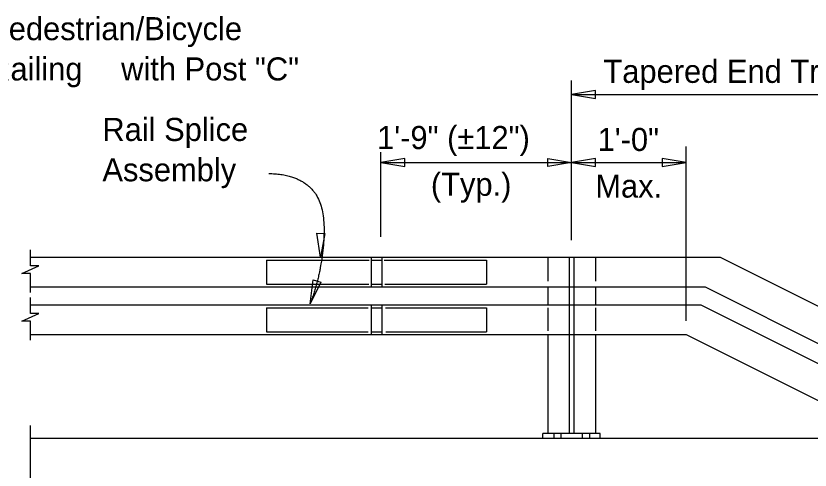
# Model space of a CAD drawing. Extents: x 120680.2 to 120752.3, y 120667.6 to 120707.3.
# Drawn here: x 120705.13 to 120712.07, y 120699.52 to 120703.49 of the extents above; entities that cross this region are included whole.
import ezdxf

# ---------------------------------------------------------------- set-up
doc = ezdxf.new("R2010")
doc.units = 0
for name, color, linetype in [('Default', 7, 'Continuous'), ('Dimension', 7, 'Continuous'), ('ParapetConc', 7, 'Continuous'), ('PedRail', 7, 'Continuous'), ('TextStructures', 7, 'Continuous')]:
    doc.layers.add(name, color=color, linetype=linetype)

msp = doc.modelspace()

# ---------------------------------------------------------------- linework, layer by layer
at = {"layer": 'Default'}
msp.add_lwpolyline([(120709.7737, 120702.2391), (120709.982, 120702.2038), (120709.7737, 120702.1686)], close=True, dxfattribs=at)
at = {"layer": 'Dimension'}
for p, q in [((120709.982, 120701.5249), (120709.982, 120702.92)), ((120710.982, 120700.8207), (120710.982, 120702.3438)), ((120708.3152, 120701.556), (120708.3152, 120702.2949))]:
    msp.add_line(p, q, dxfattribs=at)
for points in [[(120709.982, 120702.7991), (120710.1902, 120702.7638), (120710.1902, 120702.8344)], [(120708.3152, 120702.2038), (120708.5235, 120702.1686), (120708.5235, 120702.2391)], [(120709.982, 120702.2038), (120710.1902, 120702.1686), (120710.1902, 120702.2391)], [(120710.982, 120702.2038), (120710.7737, 120702.2391), (120710.7737, 120702.1686)], [(120707.8252, 120701.5859), (120707.7884, 120701.3779), (120707.7547, 120701.5864)], [(120707.7918, 120701.1593), (120707.6976, 120700.9703), (120707.7243, 120701.1798)]]:
    msp.add_lwpolyline(points, close=True, dxfattribs=at)
for points in [[(120708.3152, 120702.2038), (120709.982, 120702.2038)], [(120705.2543, 120701.069), (120705.2543, 120701.2356), (120705.1768, 120701.2356), (120705.3268, 120701.3018), (120705.2543, 120701.3018), (120705.2543, 120701.4427)], [(120705.2543, 120700.6523), (120705.2543, 120700.8189), (120705.1768, 120700.8189), (120705.3268, 120700.8852), (120705.2543, 120700.8852), (120705.2543, 120701.026)], [(120705.2532, 120698.3779), (120705.2532, 120699.2651), (120705.1757, 120699.2651), (120705.3257, 120699.3314), (120705.2532, 120699.3314), (120705.2532, 120699.907)]]:
    msp.add_lwpolyline(points, dxfattribs=at)
at = {"layer": 'ParapetConc'}
for p, q in [((120705.2532, 120699.7946), (120708.0179, 120699.7946)), ((120708.0179, 120699.7946), (120715.7028, 120699.7946))]:
    msp.add_line(p, q, dxfattribs=at)
at = {"layer": 'PedRail'}
for p, q in [((120705.2543, 120701.3779), (120708.0179, 120701.3779)), ((120708.0179, 120701.3779), (120711.2793, 120701.3779)), ((120708.2311, 120701.3779), (120708.2311, 120701.1174)), ((120708.3228, 120701.3779), (120708.3228, 120701.1174)), ((120709.7736, 120701.3779), (120709.7736, 120701.1671)), ((120709.9611, 120701.3779), (120709.9611, 120700.7007)), ((120710.0028, 120701.3779), (120710.0028, 120700.7007)), ((120710.1903, 120701.3779), (120710.1903, 120701.1671)), ((120711.2793, 120701.3779), (120714.3627, 120699.8362)), ((120707.3175, 120701.3529), (120707.3175, 120701.1424)), ((120707.3175, 120701.3529), (120708.2142, 120701.3529)), ((120708.2311, 120701.3529), (120708.3228, 120701.3529)), ((120708.3436, 120701.3529), (120709.2382, 120701.3529)), ((120709.2382, 120701.3529), (120709.2382, 120701.1424)), ((120705.2543, 120701.1174), (120708.0179, 120701.1174)), ((120707.3175, 120701.1424), (120708.2089, 120701.1424)), ((120708.0179, 120701.1174), (120711.1491, 120701.1174)), ((120708.2311, 120701.1424), (120708.3228, 120701.1424)), ((120708.3488, 120701.1424), (120709.2382, 120701.1424)), ((120709.7736, 120701.1084), (120709.7736, 120700.9613)), ((120710.1903, 120701.1084), (120710.1903, 120700.9613)), ((120711.1491, 120701.1174), (120713.7114, 120699.8362)), ((120705.2543, 120700.9613), (120707.769, 120700.9613)), ((120707.769, 120700.9613), (120711.1122, 120700.9613)), ((120708.2311, 120700.9613), (120708.2311, 120700.7007)), ((120708.3228, 120700.9613), (120708.3228, 120700.7007)), ((120711.1122, 120700.9613), (120713.3622, 120699.8362)), ((120707.3175, 120700.9362), (120707.3175, 120700.7257)), ((120707.3175, 120700.9362), (120708.2047, 120700.9362)), ((120708.2311, 120700.9362), (120708.3228, 120700.9362)), ((120708.3551, 120700.9362), (120709.2382, 120700.9362)), ((120709.2382, 120700.9362), (120709.2382, 120700.7257)), ((120709.7736, 120700.9345), (120709.7736, 120700.7342)), ((120710.1903, 120700.9345), (120710.1903, 120700.7342)), ((120705.2543, 120700.7007), (120707.769, 120700.7007)), ((120707.3175, 120700.7257), (120708.2047, 120700.7257)), ((120707.769, 120700.7007), (120710.982, 120700.7007)), ((120708.2311, 120700.7257), (120708.3228, 120700.7257)), ((120708.3593, 120700.7257), (120709.2382, 120700.7257)), ((120709.7736, 120700.7007), (120709.7736, 120699.8362)), ((120709.9611, 120700.7007), (120709.9611, 120699.8362)), ((120710.0028, 120700.7007), (120710.0028, 120699.8362)), ((120710.1903, 120700.7007), (120710.1903, 120699.8362)), ((120710.982, 120700.7007), (120712.7109, 120699.8362)), ((120710.232, 120699.8362), (120709.732, 120699.8362)), ((120709.732, 120699.7946), (120709.732, 120699.8362)), ((120709.8257, 120699.8362), (120709.8257, 120699.7946)), ((120709.8882, 120699.8362), (120709.8882, 120699.7946)), ((120710.0757, 120699.8362), (120710.0757, 120699.7946)), ((120710.1382, 120699.8362), (120710.1382, 120699.7946)), ((120710.232, 120699.7946), (120710.232, 120699.8362))]:
    msp.add_line(p, q, dxfattribs=at)
at = {"layer": 'TextStructures'}
for p, q in [((120709.982, 120702.7991), (120714.0361, 120702.7991)), ((120709.982, 120702.2038), (120710.982, 120702.2038))]:
    msp.add_line(p, q, dxfattribs=at)
msp.add_open_spline([(120707.3361, 120702.1082), (120707.5727, 120702.1082), (120707.8334, 120701.854), (120707.8014, 120701.2441), (120707.6976, 120700.9703)], degree=2, dxfattribs=at)

# ---------------------------------------------------------------- texts
for s, p in [('Pedestrian/Bicycle', (120704.8842, 120703.2738)), ('Railing ', (120704.8842, 120702.9218)), ('with Post "C"', (120706.0461, 120702.9218)), ('Tapered End Transition', (120710.26, 120702.9007)), ('Rail Splice', (120705.8823, 120702.3929)), ('1\'-9" (±12")', (120708.2825, 120702.3223)), ('1\'-0"', (120710.2091, 120702.3055)), ('Assembly', (120705.8823, 120702.0409)), ('(Typ.)', (120708.7524, 120701.9138)), ('Max.', (120710.1891, 120701.8983))]:
    msp.add_text(s, height=0.2016, dxfattribs=at).set_placement(p)

doc.saveas('drawing.dxf')
